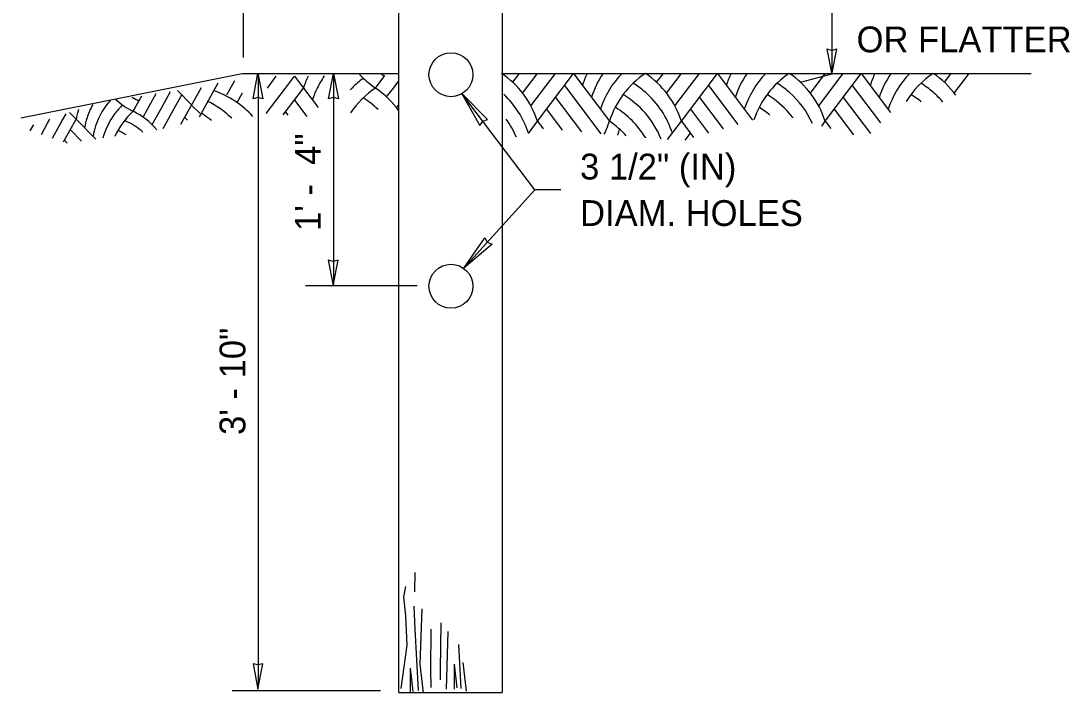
# Model space of a CAD drawing. Extents: x 1312564.2 to 1312581.5, y 1207298.4 to 1207352.6.
# Drawn here: x 1312572.922 to 1312576.174, y 1207315.434 to 1207317.519 of the extents above; entities that cross this region are included whole.
import ezdxf

# ---------------------------------------------------------------- set-up
doc = ezdxf.new("R2010")
doc.units = 0
for name, color, linetype in [('Level 11', 7, 'Continuous'), ('Level 15', 7, 'Continuous'), ('Level 20', 7, 'Continuous'), ('Level 3', 7, 'Continuous')]:
    doc.layers.add(name, color=color, linetype=linetype)

msp = doc.modelspace()

# ---------------------------------------------------------------- linework, layer by layer
at = {"layer": 'Level 11'}
for p, q in [((1312574.2659, 1207315.446), (1312574.2665, 1207315.5235)), ((1312574.1295, 1207315.4341), (1312574.1301, 1207315.5115))]:
    msp.add_line(p, q, dxfattribs=at)
for points in [[(1312574.1431, 1207315.748), (1312574.1442, 1207315.8077)], [(1312574.1009, 1207315.4483), (1312574.1196, 1207315.5823), (1312574.1152, 1207315.6734), (1312574.1094, 1207315.732), (1312574.1155, 1207315.7644)], [(1312574.1541, 1207315.4424), (1312574.1443, 1207315.6322), (1312574.1406, 1207315.7031)], [(1312574.1599, 1207315.5235), (1312574.1659, 1207315.6949)], [(1312574.2226, 1207315.5059), (1312574.2246, 1207315.6523)], [(1312574.1924, 1207315.5059), (1312574.1934, 1207315.6325)], [(1312574.2414, 1207315.4465), (1312574.2459, 1207315.6248)], [(1312574.2869, 1207315.4479), (1312574.2798, 1207315.585)], [(1312574.17, 1207315.4342), (1312574.1599, 1207315.5235)], [(1312574.2747, 1207315.4504), (1312574.2665, 1207315.5235)], [(1312574.3028, 1207315.4398), (1312574.2927, 1207315.529)], [(1312574.1383, 1207315.4385), (1312574.1301, 1207315.5115)], [(1312574.1933, 1207315.4509), (1312574.1924, 1207315.5059)], [(1312574.2226, 1207315.4746), (1312574.2226, 1207315.5059)]]:
    msp.add_lwpolyline(points, dxfattribs=at)
at = {"layer": 'Level 15'}
for p, q in [((1312575.4361, 1207318.7373), (1312575.4361, 1207317.3525)), ((1312573.612, 1207317.4054), (1312573.612, 1207317.5935)), ((1312575.4361, 1207317.479), (1312575.4361, 1207317.3525)), ((1312572.922, 1207317.2188), (1312573.6077, 1207317.3563)), ((1312573.6077, 1207317.3563), (1312574.0909, 1207317.3563)), ((1312573.612, 1207317.3563), (1312574.0909, 1207317.3563)), ((1312573.6578, 1207317.3563), (1312573.6578, 1207315.4575)), ((1312573.8913, 1207317.3539), (1312573.8913, 1207316.7012)), ((1312574.4117, 1207317.3563), (1312575.8642, 1207317.3563)), ((1312575.8642, 1207317.3563), (1312576.0539, 1207317.3563)), ((1312574.5152, 1207316.9951), (1312574.2945, 1207316.7518)), ((1312573.8036, 1207316.6986), (1312574.1503, 1207316.6986)), ((1312573.5767, 1207315.4416), (1312574.0363, 1207315.4416))]:
    msp.add_line(p, q, dxfattribs=at)
for points in [[(1312575.4361, 1207317.3525), (1312575.4516, 1207317.4313), (1312575.4361, 1207317.4276), (1312575.4207, 1207317.4313)], [(1312573.6568, 1207317.3565), (1312573.6722, 1207317.2778), (1312573.6568, 1207317.2815), (1312573.6414, 1207317.2778)], [(1312573.8906, 1207317.3563), (1312573.9061, 1207317.2776), (1312573.8906, 1207317.2812), (1312573.8752, 1207317.2776)], [(1312574.2875, 1207317.2948), (1312574.3447, 1207317.1947), (1312574.3534, 1207317.208), (1312574.3686, 1207317.2128)], [(1312574.2945, 1207316.7518), (1312574.3602, 1207316.8465), (1312574.3678, 1207316.8326), (1312574.3824, 1207316.8264)], [(1312573.8894, 1207316.698), (1312573.9049, 1207316.7768), (1312573.8894, 1207316.7731), (1312573.874, 1207316.7768)], [(1312573.6568, 1207315.4461), (1312573.6722, 1207315.5249), (1312573.6568, 1207315.5212), (1312573.6414, 1207315.5249)]]:
    msp.add_lwpolyline(points, close=True, dxfattribs=at)
msp.add_lwpolyline([(1312574.5954, 1207316.9951), (1312574.5152, 1207316.9951), (1312574.2875, 1207317.2948)], dxfattribs=at)
for centre in [(1312574.255, 1207317.3521), (1312574.255, 1207316.6961)]:
    msp.add_circle(centre, 0.0681, dxfattribs=at)
at = {"layer": 'Level 20'}
for p, q in [((1312573.6862, 1207317.3108), (1312573.7135, 1207317.3472)), ((1312573.7419, 1207317.3108), (1312573.7696, 1207317.3476)), ((1312573.7701, 1207317.3477), (1312573.7977, 1207317.3108)), ((1312574.0208, 1207317.3108), (1312574.05, 1207317.3497)), ((1312574.4466, 1207317.3286), (1312574.4674, 1207317.3563)), ((1312574.4773, 1207317.2951), (1312574.5232, 1207317.3563)), ((1312574.5031, 1207317.2552), (1312574.579, 1207317.3563)), ((1312574.5232, 1207317.2076), (1312574.6347, 1207317.3563)), ((1312574.6347, 1207317.3563), (1312574.7463, 1207317.2076)), ((1312574.8928, 1207317.3286), (1312574.9136, 1207317.3563)), ((1312574.9234, 1207317.2951), (1312574.9693, 1207317.3563)), ((1312574.9492, 1207317.2552), (1312575.0251, 1207317.3563)), ((1312574.9693, 1207317.2076), (1312575.0809, 1207317.3563)), ((1312575.0809, 1207317.3563), (1312575.19, 1207317.2108)), ((1312575.3389, 1207317.3286), (1312575.4398, 1207317.3563)), ((1312575.3695, 1207317.2951), (1312575.4155, 1207317.3563)), ((1312575.3954, 1207317.2552), (1312575.4712, 1207317.3563)), ((1312575.4155, 1207317.2076), (1312575.527, 1207317.3563)), ((1312575.527, 1207317.3563), (1312575.6177, 1207317.2354)), ((1312575.785, 1207317.3286), (1312575.8058, 1207317.3563)), ((1312575.8156, 1207317.2951), (1312575.8616, 1207317.3563)), ((1312573.418, 1207317.1984), (1312573.4812, 1207317.3126)), ((1312573.4751, 1207317.2218), (1312573.5335, 1207317.3275)), ((1312573.5599, 1207317.2898), (1312573.5847, 1207317.3346)), ((1312573.6824, 1207317.2315), (1312573.7419, 1207317.3108)), ((1312573.7353, 1207317.2276), (1312573.7977, 1207317.3108)), ((1312573.7977, 1207317.3108), (1312573.8431, 1207317.2503)), ((1312574.0557, 1207317.2831), (1312574.0765, 1207317.3108)), ((1312574.0765, 1207317.3108), (1312574.0936, 1207317.3335)), ((1312574.6069, 1207317.3192), (1312574.7193, 1207317.1692)), ((1312575.053, 1207317.3192), (1312575.1444, 1207317.1973)), ((1312575.4991, 1207317.3192), (1312575.5863, 1207317.2029)), ((1312573.2698, 1207317.2386), (1312573.2966, 1207317.287)), ((1312573.314, 1207317.2448), (1312573.341, 1207317.2936)), ((1312573.3582, 1207317.2509), (1312573.3854, 1207317.3001)), ((1312573.4024, 1207317.2571), (1312573.4204, 1207317.2896)), ((1312573.4068, 1207317.3033), (1312573.4521, 1207317.2577)), ((1312573.592, 1207317.2659), (1312573.6088, 1207317.2962)), ((1312573.7698, 1207317.2736), (1312573.8084, 1207317.2221)), ((1312574.579, 1207317.282), (1312574.6596, 1207317.1745)), ((1312575.0251, 1207317.282), (1312575.0987, 1207317.1838)), ((1312575.4712, 1207317.282), (1312575.5557, 1207317.1693)), ((1312573.3006, 1207317.2205), (1312573.314, 1207317.2448)), ((1312573.3285, 1207317.1973), (1312573.3582, 1207317.2509)), ((1312573.3625, 1207317.185), (1312573.4024, 1207317.2571)), ((1312573.4519, 1207317.2571), (1312573.4771, 1207317.2316)), ((1312574.0863, 1207317.2495), (1312574.0936, 1207317.2592)), ((1312574.5511, 1207317.2448), (1312574.5998, 1207317.1798)), ((1312574.9972, 1207317.2448), (1312575.053, 1207317.1704)), ((1312575.4433, 1207317.2448), (1312575.503, 1207317.1652)), ((1312573.0047, 1207317.2018), (1312573.0114, 1207317.214)), ((1312573.0197, 1207317.1553), (1312573.0489, 1207317.208)), ((1312573.0489, 1207317.208), (1312573.0617, 1207317.2311)), ((1312573.0541, 1207317.1437), (1312573.0931, 1207317.2141)), ((1312573.0725, 1207317.2348), (1312573.0931, 1207317.2141)), ((1312573.0931, 1207317.2141), (1312573.1541, 1207317.1526)), ((1312573.4291, 1207317.2201), (1312573.4378, 1207317.2113)), ((1312573.7419, 1207317.2364), (1312573.7494, 1207317.2265)), ((1312574.4952, 1207317.1703), (1312574.5232, 1207317.2076)), ((1312574.5232, 1207317.2076), (1312574.5408, 1207317.1842)), ((1312574.9267, 1207317.1507), (1312574.9693, 1207317.2076)), ((1312574.9693, 1207317.2076), (1312575.0074, 1207317.1569)), ((1312575.4045, 1207317.193), (1312575.4155, 1207317.2076)), ((1312575.4155, 1207317.2076), (1312575.4323, 1207317.1851)), ((1312572.951, 1207317.1785), (1312572.9605, 1207317.1957)), ((1312572.9605, 1207317.1957), (1312572.9611, 1207317.1968)), ((1312572.9854, 1207317.1669), (1312573.0047, 1207317.2018)), ((1312573.0751, 1207317.1816), (1312573.1099, 1207317.1464)), ((1312573.0571, 1207317.149), (1312573.0657, 1207317.1403)), ((1312574.9813, 1207317.1492), (1312574.9972, 1207317.1704))]:
    msp.add_line(p, q, dxfattribs=at)
for centre, radius, start, end in [((1312574.0667, 1207317.2253), 0.2822, 154.2287, 162.3566), ((1312574.0946, 1207317.1881), 0.2822, 145.4016, 154.2266), ((1312574.1503, 1207317.1137), 0.2822, 126.331, 135.7128), ((1312574.1782, 1207317.5451), 0.2822, 222.8026, 236.0964), ((1312574.2061, 1207317.5822), 0.2822, 233.9894, 236.0964), ((1312574.2542, 1207317.1221), 0.2822, 17.6434, 56.0954), ((1312574.9316, 1207317.2336), 0.2822, 154.2266, 162.3566), ((1312574.9595, 1207317.1964), 0.2822, 145.491, 162.3566), ((1312574.9874, 1207317.1593), 0.2822, 135.7127, 162.3566), ((1312575.0152, 1207317.1221), 0.2822, 123.9036, 162.3566), ((1312574.7004, 1207317.1221), 0.2822, 17.6434, 56.0963), ((1312575.3777, 1207317.2336), 0.2822, 154.2266, 162.3566), ((1312575.4056, 1207317.1964), 0.2822, 145.491, 162.3566), ((1312575.4335, 1207317.1593), 0.2822, 135.7127, 162.3566), ((1312575.4614, 1207317.1221), 0.2822, 123.9036, 161.4415), ((1312575.1465, 1207317.1221), 0.2822, 17.6434, 56.0963), ((1312575.8238, 1207317.2336), 0.2822, 154.2266, 162.3566), ((1312575.8517, 1207317.1964), 0.2822, 145.491, 162.3566), ((1312575.8796, 1207317.1593), 0.2822, 135.7127, 162.3566), ((1312575.9075, 1207317.1221), 0.2822, 123.9036, 148.6157), ((1312575.5926, 1207317.1221), 0.2822, 36.1363, 56.0963), ((1312574.0946, 1207317.1881), 0.2822, 154.2265, 162.3566), ((1312574.1503, 1207317.1137), 0.2822, 135.7127, 137.4154), ((1312574.1782, 1207317.0765), 0.2822, 123.9036, 146.0386), ((1312573.8633, 1207317.0765), 0.2822, 35.3583, 56.0963), ((1312574.6725, 1207317.0849), 0.2822, 48.9597, 58.5465), ((1312575.1186, 1207317.0849), 0.2822, 48.9597, 58.5465), ((1312575.5647, 1207317.0849), 0.2822, 48.9597, 58.5465), ((1312573.368, 1207317.1231), 0.2258, 138.5624, 153.3983), ((1312573.3688, 1207317.4416), 0.2258, 227.4903, 244.0036), ((1312573.3868, 1207317.4741), 0.2258, 237.9898, 244.0036), ((1312573.4299, 1207317.0348), 0.2822, 41.7401, 71.0876), ((1312573.8354, 1207317.0394), 0.2822, 46.6996, 58.5465), ((1312574.2264, 1207317.0849), 0.2822, 17.6434, 47.1074), ((1312574.6446, 1207317.0477), 0.2822, 40.9413, 59.3021), ((1312574.6725, 1207317.0849), 0.2822, 17.6434, 48.9597), ((1312575.0907, 1207317.0477), 0.2822, 40.9413, 59.3021), ((1312575.1186, 1207317.0849), 0.2822, 24.3021, 48.9597), ((1312575.5369, 1207317.0477), 0.2822, 51.3504, 59.3021), ((1312575.5647, 1207317.0849), 0.2822, 40.1338, 48.9597), ((1312573.3156, 1207317.1759), 0.2258, 162.3619, 170.2638), ((1312573.3418, 1207317.1495), 0.2258, 150.8896, 162.1338), ((1312573.3942, 1207317.0967), 0.2258, 134.2382, 143.62), ((1312573.3771, 1207317.0163), 0.2822, 45.4037, 64.0036), ((1312574.6167, 1207317.0105), 0.2822, 31.3316, 58.4874), ((1312575.0628, 1207317.0105), 0.2822, 50.0105, 58.4874), ((1312573.3418, 1207317.1495), 0.2258, 162.1338, 170.2638), ((1312573.368, 1207317.1231), 0.2258, 153.3982, 170.2638), ((1312573.3942, 1207317.0967), 0.2258, 143.6199, 164.8773), ((1312573.4204, 1207317.0703), 0.2258, 131.8108, 156.378), ((1312573.1529, 1207317.0032), 0.2258, 56.8669, 66.4537), ((1312573.1709, 1207317.0357), 0.2258, 40.2821, 64.0036), ((1312573.3306, 1207316.9942), 0.2822, 49.7746, 57.7344), ((1312574.1985, 1207317.0477), 0.2822, 23.2085, 36.0675), ((1312574.4773, 1207317.2932), 0.2822, 333.7173, 342.3566), ((1312574.5888, 1207316.9734), 0.2822, 41.9711, 56.0964), ((1312574.6446, 1207317.0477), 0.2822, 21.7961, 40.9414), ((1312575.0907, 1207317.0477), 0.2822, 37.0951, 40.9414), ((1312573.1349, 1207316.9706), 0.2258, 59.7553, 67.2094), ((1312573.1529, 1207317.0032), 0.2258, 49.2797, 56.867), ((1312574.5052, 1207317.256), 0.2822, 341.08, 345.0113), ((1312574.6167, 1207317.0105), 0.2822, 31.22, 31.3317)]:
    msp.add_arc(centre, radius, start, end, dxfattribs=at)
at = {"layer": 'Level 3'}
msp.add_line((1312574.0936, 1207315.4355), (1312574.4141, 1207315.4355), dxfattribs=at)
for points in [[(1312574.0936, 1207317.408), (1312574.0936, 1207318.7777), (1312574.4141, 1207318.7777), (1312574.4141, 1207317.4075)], [(1312574.0936, 1207315.4355), (1312574.0936, 1207317.408)], [(1312574.4141, 1207317.4075), (1312574.4141, 1207315.4355)]]:
    msp.add_lwpolyline(points, dxfattribs=at)

# ---------------------------------------------------------------- texts
at = {"layer": 'Level 20'}
for s, height, p in [('OR FLATTER', 0.08012, (1312575.5126, 1207317.4216)), ('3 1/2" (IN) ', 0.080117, (1312574.6554, 1207317.0271)), ('DIAM. HOLES', 0.080117, (1312574.6554, 1207316.8829))]:
    msp.add_text(s, height=height, dxfattribs=at).set_placement(p)
for s, p in [('1\' -  4"', (1312573.8512, 1207316.8675)), ('3\' - 10"', (1312573.6178, 1207316.2348))]:
    msp.add_text(s, height=0.08012, rotation=90, dxfattribs=at).set_placement(p)

doc.saveas('drawing.dxf')
